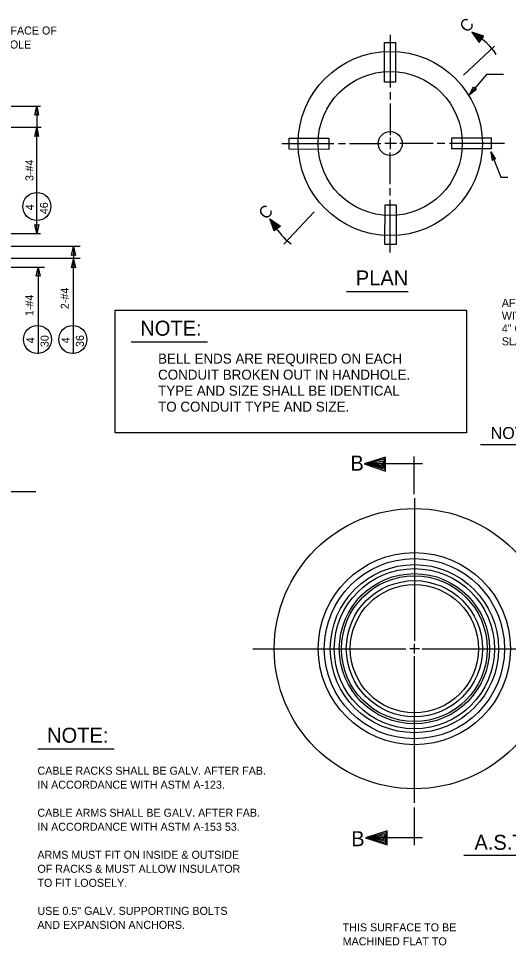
# Model space of a CAD drawing. Extents: x 19188 to 19495, y 20866 to 21061.
# Drawn here: x 19367.5 to 19418.8, y 20963.3 to 21060.3 of the extents above; entities that cross this region are included whole.
import ezdxf

# ---------------------------------------------------------------- set-up
doc = ezdxf.new("R2010")
doc.units = 0
doc.layers.add('G-ANNO-NOTE', color=7, linetype='Continuous')

msp = doc.modelspace()

# ---------------------------------------------------------------- linework, layer by layer
at = {"layer": 'G-ANNO-NOTE'}
for p, q in [((19415.724, 21057.847), (19416.093, 21058.345)), ((19417.332, 21057.375), (19414.075, 21054.329)), ((19353.375, 21051.113), (19369.818, 21051.113)), ((19369.427, 21051.097), (19369.427, 21050.245)), ((19353.41, 21048.893), (19369.889, 21048.893)), ((19369.424, 21048.853), (19369.424, 21048.001)), ((19407.071, 21047.195), (19405.856, 21047.195)), ((19406.41, 21047.821), (19406.41, 21046.596)), ((19395.264, 21036.657), (19398.437, 21040.049)), ((19369.427, 21037.791), (19369.427, 21038.644)), ((19394.82, 21038.52), (19394.322, 21038.151)), ((19353.41, 21037.791), (19369.818, 21037.791)), ((19373.976, 21036.43), (19362.109, 21036.43)), ((19373.265, 21036.402), (19373.265, 21035.173)), ((19373.265, 21036.402), (19373.265, 21035.549)), ((19373.976, 21035.173), (19362.18, 21035.173)), ((19373.265, 21025.193), (19373.265, 21035.098)), ((19373.265, 21035.098), (19373.265, 21034.245)), ((19370.237, 21034.231), (19362.323, 21034.231)), ((19369.573, 21034.231), (19369.573, 21025.193)), ((19369.573, 21034.231), (19369.573, 21033.378)), ((19401.842, 21031.702), (19408.293, 21031.702)), ((19379.292, 21026.444), (19387.276, 21026.444)), ((19415.838, 21015.7), (19422.298, 21015.7)), ((19408.912, 21010.501), (19408.912, 21014.453)), ((19409.785, 21013.662), (19404.306, 21013.662)), ((19324.516, 21010.791), (19369.32, 21010.791)), ((19408.935, 21010.073), (19408.935, 20995.169)), ((19408.935, 20993.84), (19408.935, 20994.83)), ((19392.028, 20994.333), (19408.041, 20994.333)), ((19409.459, 20994.333), (19408.444, 20994.333)), ((19409.734, 20994.333), (19425.638, 20994.333)), ((19408.935, 20978.197), (19408.935, 20993.56)), ((19369.54, 20983.852), (19377.524, 20983.852)), ((19408.912, 20977.715), (19408.912, 20973.764)), ((19409.785, 20974.554), (19404.306, 20974.554)), ((19414.121, 20972.719), (19455.447, 20972.719))]:
    msp.add_line(p, q, dxfattribs=at)
for points in [[(19415.711, 21057.752), (19416.205, 21058.417), (19414.93, 21058.857), (19415.711, 21057.752)], [(19406.41, 21058.555), (19406.41, 21053.049)], [(19415.692, 21057.899), (19416.062, 21058.398), (19415.106, 21058.728), (19415.692, 21057.899)], [(19415.695, 21057.991), (19415.972, 21058.365), (19415.256, 21058.613), (19415.695, 21057.991)], [(19415.696, 21058.072), (19415.904, 21058.353), (19415.367, 21058.539), (19415.696, 21058.072)], [(19415.702, 21058.144), (19415.842, 21058.333), (19415.479, 21058.459), (19415.702, 21058.144)], [(19415.705, 21058.213), (19415.783, 21058.319), (19415.581, 21058.388), (19415.705, 21058.213)], [(19418.275, 21054.424), (19416.484, 21054.424), (19414.692, 21052.322)], [(19406.41, 21052.574), (19406.41, 21051.814)], [(19369.427, 21050.244), (19369.223, 21050.17), (19369.427, 21051.097), (19369.621, 21050.172), (19369.427, 21050.244)], [(19369.427, 21051.097), (19369.424, 21048.854)], [(19406.41, 21051.396), (19406.41, 21048.079)], [(19369.424, 21048), (19369.221, 21047.925), (19369.424, 21048.853), (19369.619, 21047.928), (19369.424, 21048)], [(19369.427, 21037.791), (19369.424, 21048.853)], [(19395.055, 21047.195), (19400.513, 21047.195)], [(19400.983, 21047.195), (19401.737, 21047.195)], [(19402.151, 21047.195), (19405.439, 21047.195)], [(19410.883, 21047.195), (19407.419, 21047.195)], [(19412.113, 21047.195), (19411.319, 21047.195)], [(19418.359, 21047.195), (19412.609, 21047.195)], [(19406.41, 21042.934), (19406.41, 21046.241)], [(19416.916, 21046.327), (19417.966, 21043.669), (19418.708, 21043.669)], [(19406.41, 21041.76), (19406.41, 21042.518)], [(19406.41, 21035.797), (19406.41, 21041.286)], [(19369.427, 21038.645), (19369.631, 21038.719), (19369.427, 21037.791), (19369.232, 21038.717), (19369.427, 21038.645)], [(19394.916, 21038.533), (19394.251, 21038.04), (19393.81, 21039.314), (19394.916, 21038.533)], [(19394.768, 21038.552), (19394.269, 21038.182), (19393.939, 21039.138), (19394.768, 21038.552)], [(19394.676, 21038.549), (19394.302, 21038.272), (19394.054, 21038.989), (19394.676, 21038.549)], [(19394.595, 21038.548), (19394.315, 21038.34), (19394.129, 21038.878), (19394.595, 21038.548)], [(19394.524, 21038.543), (19394.334, 21038.402), (19394.209, 21038.765), (19394.524, 21038.543)], [(19394.454, 21038.539), (19394.349, 21038.461), (19394.279, 21038.663), (19394.454, 21038.539)], [(19373.265, 21035.549), (19373.061, 21035.475), (19373.265, 21036.402), (19373.46, 21035.477), (19373.265, 21035.549)], [(19373.265, 21034.245), (19373.061, 21034.171), (19373.265, 21035.098), (19373.46, 21034.172), (19373.265, 21034.245)], [(19369.573, 21033.377), (19369.369, 21033.303), (19369.573, 21034.231), (19369.767, 21033.305), (19369.573, 21033.377)], [(19405.925, 21012.923), (19405.925, 21014.372), (19403.674, 21013.662), (19405.925, 21012.923)], [(19403.977, 21013.662), (19405.825, 21013.1), (19405.816, 21014.185), (19403.986, 21013.662)], [(19405.514, 21013.623), (19403.86, 21013.657)], [(19404.324, 21013.662), (19405.706, 21013.288), (19405.697, 21013.968), (19404.342, 21013.662)], [(19404.736, 21013.643), (19405.55, 21013.475), (19405.55, 21013.741), (19404.736, 21013.643)], [(19406.083, 20973.814), (19406.083, 20975.263), (19403.832, 20974.554), (19406.083, 20973.814)], [(19405.672, 20974.514), (19404.018, 20974.548)], [(19404.134, 20974.554), (19405.983, 20973.992), (19405.973, 20975.076), (19404.143, 20974.554)], [(19404.482, 20974.554), (19405.864, 20974.179), (19405.855, 20974.859), (19404.501, 20974.554)], [(19404.894, 20974.534), (19405.708, 20974.367), (19405.708, 20974.633), (19404.894, 20974.534)]]:
    msp.add_lwpolyline(points, dxfattribs=at)
for points in [[(19405.792, 21053.623), (19405.798, 21057.756), (19406.959, 21057.754), (19406.953, 21053.621)], [(19415.424, 21052.877), (19415.227, 21052.95), (19414.692, 21052.322), (19415.129, 21053.125), (19415.227, 21052.95), (19414.692, 21052.322)], [(19399.981, 21046.58), (19395.848, 21046.588), (19395.85, 21047.748), (19399.983, 21047.74)], [(19412.838, 21047.804), (19416.971, 21047.793), (19416.968, 21046.633), (19412.835, 21046.643)], [(19417.062, 21045.42), (19417.219, 21045.56), (19416.916, 21046.327), (19417.42, 21045.564), (19417.219, 21045.56), (19416.916, 21046.327)], [(19407.022, 21040.766), (19407.013, 21036.633), (19405.852, 21036.635), (19405.861, 21040.769)], [(19377.619, 21029.768), (19414.403, 21029.768), (19414.403, 21016.924), (19377.619, 21016.924)]]:
    msp.add_lwpolyline(points, close=True, dxfattribs=at)
for centre, radius in [((19406.409, 21047.195), 9.635), ((19406.409, 21047.195), 7.541), ((19406.409, 21047.195), 1.257), ((19369.437, 21040.603), 1.466), ((19369.5, 21026.686), 1.466), ((19373.193, 21026.686), 1.466), ((19408.935, 20994.333), 14.662), ((19408.935, 20994.333), 10.054), ((19408.935, 20994.333), 9.426), ((19408.935, 20994.333), 8.797), ((19408.935, 20994.333), 8.379), ((19408.935, 20994.333), 7.855), ((19408.935, 20994.333), 7.624), ((19408.935, 20994.333), 7.122), ((19408.935, 20994.333), 6.703)]:
    msp.add_circle(centre, radius, dxfattribs=at)
for centre, start, end in [((19412.756, 21053.616), 31.61175, 62.97283), ((19399.221, 21041.24), 207.02717, 234.81207)]:
    msp.add_arc(centre, 5.546, start, end, dxfattribs=at)

# ---------------------------------------------------------------- texts
for s, height, rotation, p in [('C', 1.257, 45, (19414.414, 21058.715)), ('3-#4', 0.8379, 90, (19369.075, 21043.271)), ('4', 0.838, 90, (19369.108, 21040.205)), ('46', 0.8379, 90, (19370.598, 21039.8)), ('C', 1.257, 45, (19393.385, 21039.16)), ('2-#4', 0.8379, 90, (19372.775, 21029.863)), ('1-#4', 0.8379, 90, (19369.075, 21029.137)), ('4', 0.838, 90, (19369.171, 21026.288)), ('30', 0.8379, 90, (19370.662, 21025.89)), ('4', 0.838, 90, (19372.863, 21026.288)), ('36', 0.8379, 90, (19374.353, 21025.903))]:
    msp.add_text(s, height=height, rotation=rotation, dxfattribs=at).set_placement(p)
for s, height, p in [('INSIDE FACE OF', 0.83785, (19362.625, 21058.598)), ('HANDHOLE', 0.8379, (19362.625, 21057.132)), ('PLAN', 1.571, (19402.805, 21032.341)), ('AFTER LEVELING HANDHOLE', 0.83785, (19418.081, 21030.099)), ('WITH 8" BRICKS, POUR ', 0.83785, (19418.081, 21028.759)), ('NOTE:', 1.571, (19380.254, 21027.083)), ('4" CONCRETE FLOOR', 0.83785, (19418.081, 21027.418)), ('SLAB (39"0)', 0.83785, (19418.081, 21026.077)), ('BELL ENDS ARE REQUIRED ON EACH', 1.04732, (19382.117, 21024.159)), ('CONDUIT BROKEN OUT IN HANDHOLE.', 1.04732, (19382.117, 21022.483)), ('TYPE AND SIZE SHALL BE IDENTICAL', 1.04732, (19382.117, 21020.807)), ('TO CONDUIT TYPE AND SIZE.', 1.04732, (19382.117, 21019.132)), ('NOTE:', 1.2568, (19416.915, 21016.271)), ('B', 1.571, (19402.241, 21012.968)), ('NOTE:', 1.571, (19370.503, 20984.492)), ('CABLE RACKS SHALL BE GALV. AFTER FAB.', 0.83785, (19369.495, 20981.147)), ('IN ACCORDANCE WITH ASTM A-123.', 0.83785, (19369.495, 20979.681)), ('CABLE ARMS SHALL BE GALV. AFTER FAB.', 0.83785, (19369.495, 20976.748)), ('IN ACCORDANCE WITH ASTM A-153 53.', 0.83785, (19369.495, 20975.281)), ('B', 1.571, (19402.324, 20973.666)), ('A.S.T.M. CLASS 20 OR 30 GRAY IRON', 1.57098, (19415.215, 20973.287)), ('ARMS MUST FIT ON INSIDE & OUTSIDE', 0.83785, (19369.495, 20972.348)), ('OF RACKS & MUST ALLOW INSULATOR', 0.83785, (19369.495, 20970.882)), ('TO FIT LOOSELY.', 0.83785, (19369.495, 20969.415)), ('USE 0.5" GALV. SUPPORTING BOLTS ', 0.83785, (19369.495, 20966.482)), ('AND EXPANSION ANCHORS.', 0.83785, (19369.495, 20965.016)), ('THIS SURFACE TO BE', 0.83785, (19401.431, 20964.757)), ('MACHINED FLAT TO', 0.83785, (19401.431, 20963.291))]:
    msp.add_text(s, height=height, dxfattribs=at).set_placement(p)

doc.saveas('drawing.dxf')
